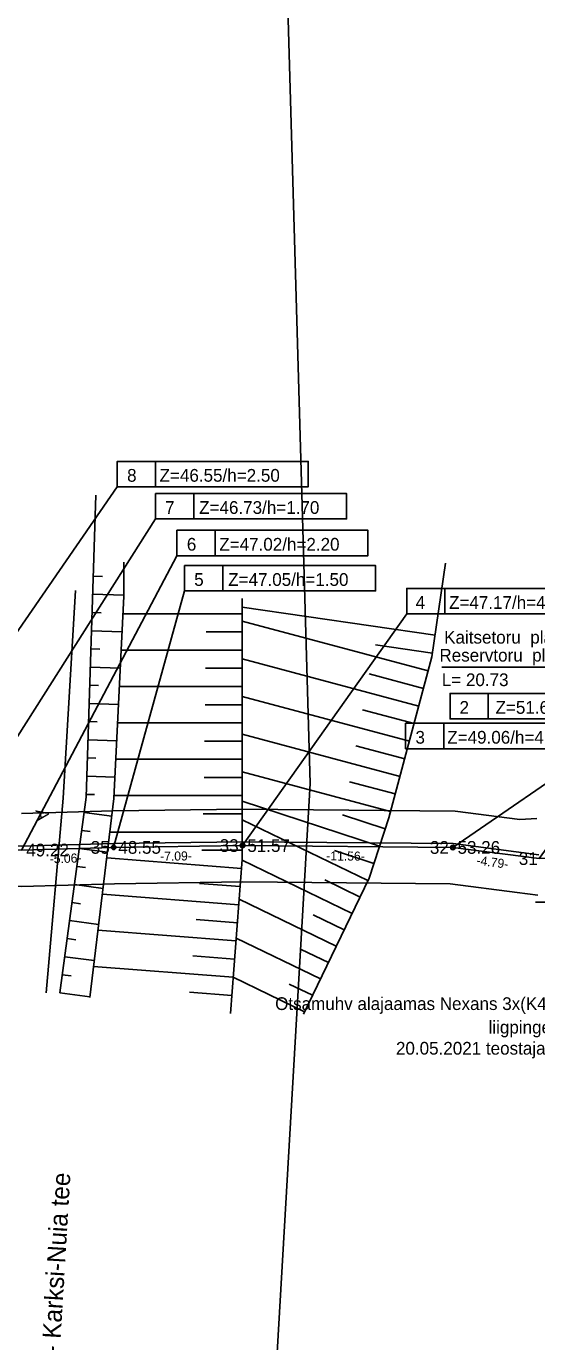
# Model space of a CAD drawing. Extents: x 592082 to 595437, y 6463338 to 6467739.
# Drawn here: x 592357.1 to 592385.2, y 6466209.4 to 6466281.7 of the extents above; entities that cross this region are included whole.
import ezdxf

# ---------------------------------------------------------------- set-up
doc = ezdxf.new("R2010")
doc.units = 0
for name, color, linetype in [('ABIJOONIS', 7, 'Continuous'), ('JOONSIDE', 7, 'Continuous'), ('KOORDPUNKT', 7, 'Continuous'), ('KPKAABEL', 7, 'Continuous'), ('MOOTKORG-EH2000', 7, 'Continuous'), ('MOOTMPUNKT', 7, 'Continuous'), ('MOOTNR', 7, 'Continuous'), ('MOOTPIIR', 7, 'Continuous'), ('MPKAABEL', 7, 'Continuous'), ('PIIR', 7, 'Continuous'), ('RAJATIS', 7, 'Continuous'), ('RELJEEF', 7, 'Continuous'), ('TEE', 7, 'Continuous')]:
    doc.layers.add(name, color=color, linetype=linetype)

msp = doc.modelspace()

# ---------------------------------------------------------------- linework, layer by layer
at = {"layer": 'ABIJOONIS'}
for points in [[(592348.253, 6466236.34), (592362.102, 6466256.376), (592372.602, 6466256.376), (592372.602, 6466257.776), (592362.102, 6466257.776), (592362.102, 6466256.376)], [(592364.202, 6466256.376), (592364.202, 6466257.776)], [(592352.699, 6466236.493), (592364.207, 6466254.608), (592374.707, 6466254.608), (592374.707, 6466256.008), (592364.207, 6466256.008), (592364.207, 6466254.608)], [(592366.307, 6466254.608), (592366.307, 6466256.008)], [(592356.84, 6466236.412), (592365.386, 6466252.587), (592375.886, 6466252.587), (592375.886, 6466253.987), (592365.386, 6466253.987), (592365.386, 6466252.587)], [(592367.486, 6466252.587), (592367.486, 6466253.987)], [(592361.902, 6466236.558), (592365.807, 6466250.65), (592376.307, 6466250.65), (592376.307, 6466252.05), (592365.807, 6466252.05), (592365.807, 6466250.65)], [(592367.907, 6466250.65), (592367.907, 6466252.05)], [(592368.994, 6466236.659), (592378.015, 6466249.387), (592388.515, 6466249.387), (592388.515, 6466250.787), (592378.015, 6466250.787), (592378.015, 6466249.387)], [(592380.115, 6466249.387), (592380.115, 6466250.787)], [(592385.299, 6466235.942), (592390.897, 6466243.62), (592380.397, 6466243.62), (592380.397, 6466245.02), (592390.897, 6466245.02), (592390.897, 6466243.62)], [(592382.497, 6466243.62), (592382.497, 6466245.02)], [(592380.551, 6466236.555), (592388.455, 6466241.978), (592377.955, 6466241.978), (592377.955, 6466243.378), (592388.455, 6466243.378), (592388.455, 6466241.978)], [(592380.055, 6466241.978), (592380.055, 6466243.378)]]:
    msp.add_lwpolyline(points, dxfattribs=at)
at = {"layer": 'KOORDPUNKT'}
for centre, radius in [((592368.994, 6466236.659), 0.125), ((592361.902, 6466236.558), 0.125), ((592361.902, 6466236.558), 0.0125), ((592361.902, 6466236.558), 0.011), ((592361.902, 6466236.558), 0.00955), ((592361.902, 6466236.558), 0.00807), ((592361.902, 6466236.558), 0.00659), ((592361.902, 6466236.558), 0.00511), ((592361.902, 6466236.558), 0.00363), ((592361.902, 6466236.558), 0.00215), ((592368.994, 6466236.659), 0.0125), ((592368.994, 6466236.659), 0.011), ((592368.994, 6466236.659), 0.00955), ((592368.994, 6466236.659), 0.00807), ((592368.994, 6466236.659), 0.00659), ((592368.994, 6466236.659), 0.00511), ((592368.994, 6466236.659), 0.00363), ((592368.994, 6466236.659), 0.00215), ((592380.551, 6466236.555), 0.125), ((592380.551, 6466236.555), 0.0125), ((592380.551, 6466236.555), 0.011), ((592380.551, 6466236.555), 0.00955), ((592380.551, 6466236.555), 0.00807), ((592380.551, 6466236.555), 0.00659), ((592380.551, 6466236.555), 0.00511), ((592380.551, 6466236.555), 0.00363), ((592380.551, 6466236.555), 0.00215)]:
    msp.add_circle(centre, radius, dxfattribs=at)
at = {"layer": 'KPKAABEL'}
for points in [[(592391.614, 6466236.293), (592392.72, 6466246.471), (592379.946, 6466246.471)], [(592385.299, 6466235.942), (592380.551, 6466236.555), (592368.994, 6466236.659), (592361.902, 6466236.558), (592356.84, 6466236.412), (592352.699, 6466236.493), (592348.253, 6466236.34), (592342.047, 6466236.463), (592336.682, 6466236.454), (592334.378, 6466236.735)], [(592385.287, 6466236.152), (592380.565, 6466236.765), (592368.993, 6466236.869), (592361.897, 6466236.768), (592356.839, 6466236.622), (592352.697, 6466236.703), (592348.251, 6466236.55), (592342.049, 6466236.673), (592336.695, 6466236.664), (592334.403, 6466236.943)], [(592402.61, 6466231.398), (592402.062, 6466230.178), (592400.927, 6466230.114), (592400.376, 6466230.913), (592400.147, 6466232.765), (592392.559, 6466236.345), (592385.299, 6466235.942), (592380.551, 6466236.555), (592368.994, 6466236.659), (592361.902, 6466236.558), (592356.84, 6466236.412)]]:
    msp.add_lwpolyline(points, dxfattribs=at)
at = {"layer": 'MOOTMPUNKT'}
for centre in [(592368.994, 6466236.659), (592361.902, 6466236.558), (592380.551, 6466236.555)]:
    msp.add_circle(centre, 0.1, dxfattribs=at)
at = {"layer": 'MOOTPIIR'}
for points in [[(592327.541, 6466358.339), (592328.041, 6466352.064), (592328.938, 6466340.333), (592330.262, 6466327.274), (592330.993, 6466314.256), (592331.614, 6466299.352), (592332.306, 6466280.71), (592332.195, 6466264.059), (592331.771, 6466247.36), (592331.059, 6466237.108), (592333.486, 6466234.829), (592336.562, 6466234.454), (592342.029, 6466234.463), (592348.268, 6466234.339), (592352.714, 6466234.492), (592356.849, 6466234.411), (592361.945, 6466234.558), (592368.999, 6466234.659), (592380.413, 6466234.556)], [(592385.177, 6466238.149), (592384.233, 6466238.096), (592380.689, 6466238.554), (592368.989, 6466238.659), (592361.859, 6466238.558), (592356.831, 6466238.413)], [(592380.413, 6466234.556), (592384.087, 6466234.082), (592385.226, 6466233.935)]]:
    msp.add_lwpolyline(points, dxfattribs=at)
at = {"layer": 'MPKAABEL'}
msp.add_lwpolyline([(592389.064, 6466236.024), (592388.621, 6466233.543), (592385.091, 6466233.543)], dxfattribs=at)
at = {"layer": 'PIIR'}
msp.add_lwpolyline([(592365.98, 6466124.11), (592372.7, 6466240.06), (592368.77, 6466376.93), (592364.1, 6466392.22), (592386.8, 6466438.64), (592386.7, 6466439.56), (592467.6, 6466449.28), (592457.87, 6466368.11), (592411.88, 6466240.36), (592481.06, 6466184.88)], dxfattribs=at)
msp.add_lwpolyline([(592357.09, 6466377.87), (592364.1, 6466392.22), (592368.77, 6466376.93), (592372.7, 6466240.06), (592365.98, 6466124.11), (592354.23, 6466082.68), (592346.03, 6466093.17), (592345.81, 6466093.45), (592350.73, 6466159.48), (592352.58, 6466211.49), (592355.31, 6466303.74), (592360.11, 6466303.63), (592360.63, 6466318.19)], close=True, dxfattribs=at)
at = {"layer": 'RELJEEF'}
for p, q in [((592360.779, 6466251.466), (592361.285, 6466251.45)), ((592360.747, 6466250.467), (592362.464, 6466250.412)), ((592379.576, 6466248.217), (592368.974, 6466249.755)), ((592360.716, 6466249.467), (592361.226, 6466249.451)), ((592368.974, 6466249.401), (592362.417, 6466249.401)), ((592360.684, 6466248.468), (592362.369, 6466248.414)), ((592368.974, 6466248.401), (592366.993, 6466248.401)), ((592379.197, 6466246.256), (592368.974, 6466248.988)), ((592379.432, 6466247.227), (592376.295, 6466247.682)), ((592360.652, 6466247.468), (592361.152, 6466247.452)), ((592368.974, 6466247.401), (592362.319, 6466247.401)), ((592378.681, 6466244.324), (592368.975, 6466246.918)), ((592360.62, 6466246.469), (592362.271, 6466246.416)), ((592368.975, 6466246.401), (592366.963, 6466246.401)), ((592360.588, 6466245.469), (592361.078, 6466245.454)), ((592368.975, 6466245.401), (592362.222, 6466245.401)), ((592378.939, 6466245.29), (592375.95, 6466246.089)), ((592378.165, 6466242.392), (592368.975, 6466244.848)), ((592360.556, 6466244.47), (592362.174, 6466244.418)), ((592368.975, 6466244.401), (592366.934, 6466244.401)), ((592378.423, 6466243.358), (592375.588, 6466244.115)), ((592360.524, 6466243.47), (592361.005, 6466243.455)), ((592368.975, 6466243.401), (592362.124, 6466243.401)), ((592377.648, 6466240.46), (592368.975, 6466242.777)), ((592360.493, 6466242.471), (592362.076, 6466242.42)), ((592368.975, 6466242.401), (592366.905, 6466242.401)), ((592377.906, 6466241.426), (592375.227, 6466242.142)), ((592360.461, 6466241.471), (592360.931, 6466241.456)), ((592368.975, 6466241.401), (592362.026, 6466241.401)), ((592360.429, 6466240.472), (592361.978, 6466240.423)), ((592368.975, 6466240.401), (592366.875, 6466240.401)), ((592377.132, 6466238.527), (592368.975, 6466240.707)), ((592377.39, 6466239.494), (592374.865, 6466240.168)), ((592360.397, 6466239.472), (592360.857, 6466239.458)), ((592368.975, 6466239.401), (592361.928, 6466239.401)), ((592376.527, 6466236.621), (592368.975, 6466239.102)), ((592360.28, 6466238.48), (592361.803, 6466238.276)), ((592368.975, 6466238.401), (592366.828, 6466238.401)), ((592376.839, 6466237.572), (592374.48, 6466238.346)), ((592360.147, 6466237.489), (592360.607, 6466237.427)), ((592375.884, 6466234.729), (592368.975, 6466238.067)), ((592368.975, 6466237.401), (592361.697, 6466237.401)), ((592360.014, 6466236.498), (592361.562, 6466236.29)), ((592368.975, 6466236.401), (592366.755, 6466236.401)), ((592376.215, 6466235.671), (592374.043, 6466236.385)), ((592359.881, 6466235.507), (592360.349, 6466235.444)), ((592368.937, 6466235.403), (592361.523, 6466235.975)), ((592375.014, 6466232.928), (592368.971, 6466235.847)), ((592368.86, 6466234.406), (592366.622, 6466234.578)), ((592375.449, 6466233.829), (592373.507, 6466234.767)), ((592359.748, 6466234.516), (592361.32, 6466234.304)), ((592368.783, 6466233.409), (592361.282, 6466233.988)), ((592359.614, 6466233.525), (592360.09, 6466233.461)), ((592374.144, 6466231.127), (592368.806, 6466233.706)), ((592359.481, 6466232.533), (592361.079, 6466232.319)), ((592368.706, 6466232.412), (592366.442, 6466232.586)), ((592374.579, 6466232.028), (592372.872, 6466232.852)), ((592368.629, 6466231.415), (592361.04, 6466232.001)), ((592359.348, 6466231.542), (592359.831, 6466231.477)), ((592373.274, 6466229.326), (592368.64, 6466231.565)), ((592373.709, 6466230.227), (592372.213, 6466230.949)), ((592359.215, 6466230.551), (592360.837, 6466230.333)), ((592368.552, 6466230.418), (592366.262, 6466230.594)), ((592359.082, 6466229.56), (592359.572, 6466229.494)), ((592368.475, 6466229.42), (592360.798, 6466230.013)), ((592372.405, 6466227.525), (592368.475, 6466229.424)), ((592372.839, 6466228.426), (592371.555, 6466229.046)), ((592358.949, 6466228.569), (592360.596, 6466228.348)), ((592368.398, 6466228.423), (592366.082, 6466228.602))]:
    msp.add_line(p, q, dxfattribs=at)
for points in [[(592358.949, 6466228.569), (592360.392, 6466239.315), (592360.921, 6466255.911)], [(592360.59, 6466228.301), (592361.921, 6466239.241), (592362.464, 6466250.364), (592362.464, 6466250.884), (592362.464, 6466252.231)], [(592380.15, 6466252.175), (592379.403, 6466247.027), (592377.039, 6466238.181), (592375.952, 6466234.869), (592372.344, 6466227.4)], [(592368.321, 6466227.426), (592368.975, 6466235.896), (592368.975, 6466244.79), (592368.974, 6466250.234)]]:
    msp.add_lwpolyline(points, dxfattribs=at)
at = {"layer": 'TEE'}
msp.add_lwpolyline([(592358.189, 6466228.562), (592359.121, 6466239.268), (592359.815, 6466250.676)], dxfattribs=at)

# ---------------------------------------------------------------- texts
at = {"layer": 'ABIJOONIS'}
for s, p in [('8', (592362.644, 6466256.656)), ('Z=46.55/h=2.50', (592364.43, 6466256.656)), ('7', (592364.732, 6466254.888)), ('Z=46.73/h=1.70', (592366.605, 6466254.888)), ('6', (592365.928, 6466252.867)), ('Z=47.02/h=2.20', (592367.713, 6466252.867)), ('5', (592366.332, 6466250.93)), ('Z=47.05/h=1.50', (592368.204, 6466250.93)), ('4', (592378.505, 6466249.667)), ('Z=47.17/h=4.40', (592380.343, 6466249.667)), ('2', (592380.922, 6466243.9)), ('Z=51.67/h=1.70', (592382.9, 6466243.9)), ('3', (592378.498, 6466242.258)), ('Z=49.06/h=4.20', (592380.248, 6466242.258))]:
    msp.add_text(s, height=0.7, dxfattribs=at).set_placement(p)
at = {"layer": 'JOONSIDE'}
for s, rotation, p in [('-5.06-', 1.65209, (592358.394, 6466235.681)), ('-7.09-', 0.81592, (592364.459, 6466235.819)), ('-11.56-', 359.48442, (592373.591, 6466235.843)), ('-4.79-', 352.64341, (592381.834, 6466235.608))]:
    msp.add_text(s, height=0.5, rotation=rotation, dxfattribs=at).set_placement(p)
at = {"layer": 'KPKAABEL'}
for s, p in [('Kaitsetoru  plast D=160_450N', (592380.075, 6466247.758)), ('Reservtoru  plast D=160_450N', (592379.816, 6466246.77)), ('L= 20.73', (592379.946, 6466245.421))]:
    msp.add_text(s, height=0.7, dxfattribs=at).set_placement(p)
at = {"layer": 'MOOTKORG-EH2000'}
for s, p in [(' 49.22', (592356.84, 6466236.062)), (' 48.55', (592361.902, 6466236.208)), (' 51.57', (592368.994, 6466236.309)), (' 53.26', (592380.551, 6466236.205))]:
    msp.add_text(s, height=0.7, dxfattribs=at).set_placement(p)
at = {"layer": 'MOOTNR'}
for s, p in [('35 ', (592360.642, 6466236.208)), ('33 ', (592367.734, 6466236.309)), ('32 ', (592379.291, 6466236.205)), ('31 ', (592384.179, 6466235.592))]:
    msp.add_text(s, height=0.7, dxfattribs=at).set_placement(p)
at = {"layer": 'PIIR'}
msp.add_text('49 Imavere - Viljandi - Karksi-Nuia tee', height=1, rotation=86.5903, dxfattribs=at).set_placement((592358.193, 6466196.178))
at = {"layer": 'RAJATIS'}
for s, p in [('Otsamuhv alajaamas Nexans 3x(K430TB/G-22-95.240-W-5)', (592370.782, 6466227.619)), ('liigpingepiirikud 3x300SA-10-22N', (592382.517, 6466226.325)), ('20.05.2021 teostajad: A.Bulattsik, J.Gavrilov', (592377.426, 6466225.167))]:
    msp.add_text(s, height=0.7, dxfattribs=at).set_placement(p)
at = {"layer": 'TEE'}
msp.add_text('A', height=0.7, rotation=279.95793, dxfattribs=at).set_placement((592357.598, 6466238.601))

doc.saveas('drawing.dxf')
